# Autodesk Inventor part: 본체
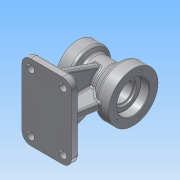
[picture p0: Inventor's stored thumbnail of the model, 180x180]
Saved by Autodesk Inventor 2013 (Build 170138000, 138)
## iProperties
Created: 2015-08
Part Number: 본체
Material: 알루미늄 6061
Document SubType Name: Modeling
Designer: ST3
Density: 2.71 g/cm^3
Mass: 1076.88 g
Surface Area: 747.39 cm^2
Volume: 397.374 cm^3
Author: ST3
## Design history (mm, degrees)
sketch "스케치1"
  geometry: L1 (0, 0)-(35.699, 0); L2 (-45, 35)-(-25, 35); L3 (-25, 35)-(-19.804, 26); L4 (-19.804, 26)-(8.315, 26); L5 (8.315, 26)-(25, 40); L6 (25, 40)-(45, 40); L7 (45, 40)-(45, 26); L8 (28, 16)-(-22, 16); L9 (-45, 20)-(-45, 35); L10 (0, 0)-(0, -43.803); L11 (-45, 20)-(-22, 20); L12 (-22, 20)-(-22, 16); L13 (45, 26)-(31, 26); L14 (31, 26)-(31, 19); L15 (31, 19)-(28, 19); L16 (28, 19)-(28, 16)
  constraints: 32 end point, 9 parallel, 4 perpendicular, 1 horizontal
  dimensions: "d4" = 20 distance of L2.start L2.end; "d5" = 20 distance of L5.end L6.end; "d7" = 40 deg angle of L4 L5; "d15" = 90 distance between parallel lines of L7 L9; "d17" = 32 diameter of L8 L1; "d18" = 80 diameter of L6 L1; "d19" = 70 diameter of L2 L1; "d23" = 52 diameter of L4 L1; "d112" = 40 diameter of L11 L1; "d113" = 52 diameter of L13 L1; "d114" = 38 diameter of L15 L1; "d115" = 3 distance of L14.end L15.end; "d116" = 60 deg angle of L4 L3
revolve "회전1" sketch "스케치1" stored, may be unused: angle "d28" = 90 deg
node "작업 평면1"
sketch "스케치2"
  geometry: L1 (-45, -35)-(-25, -35) reference; L2 (25, -40)-(45, -40) reference; L3 (-45, -90)-(-45, -78); L4 (-45, -78)-(35, -78); L5 (35, -78)-(35, -90); L6 (-45, -35)-(-45, 35) reference; L7 (-45, -90)-(35, -90); 1 further point
  constraints: 8 end point, 1 parallel, 1 perpendicular
  dimensions: "d34" = 0 distance between parallel lines of L6 L3; "d36" = 90 distance from line of point (0, 0) L7; "d37" = 80 distance of L3.end L4.end; "d38" = 12 distance of L4.end L5.end
extrude "돌출1" join sketch "스케치2" stored distance "d39" = 122; taper "d40" = 0 deg
node "작업 평면2"
sketch "스케치4"
  geometry: L1 (-45, -78)-(35, -78) reference; L2 (-45, -90)-(-45, -78) reference; L3 (-45, -78)-(35, -78) reference; L4 (35, -78)-(35, -90) reference; L5 (35, -90)-(-45, -90) reference; L6 (-45, -35)-(-25, -35) reference; L7 (-19.804, -26)-(8.315, -26) reference; L8 (25, -40)-(45, -40) reference; L9 (-25, -35)-(-19.804, -26) reference; L10 (8.315, -26)-(25, -40) reference; L11 (-35, -78)-(-35, -35); L12 (25, -78)-(31.7, -40); L13 (-35, -35)-(-35, -25.572); L14 (-35, -25.572)-(31.7, -26); L15 (31.7, -40)-(32.614, -34.816); L16 (32.614, -34.816)-(31.7, -26); 1 further point
  constraints: 12 end point, 4 point on line, 2 collinear, 1 midpoint, 1 perpendicular
  dimensions: "d42" = 10 distance between parallel lines of L11 L2; "d44" = 80 deg angle of L1 L12; "d45" = 10 distance of L1.end L12.start
extrude "돌출2" join sketch "스케치4" stored distance "d46" = 12; taper "d47" = 0 deg
sketch "스케치5"
  geometry: L1 (28.973, 0)-(0, 0) reference; 3 further points
  constraints: 3 other
extrude "돌출3" join sketch "스케치5" stored distance "d48" = 12; taper "d49" = 0 deg
sketch "스케치6"
  geometry: L1 (0, 0)-(28.973, 0) reference; 3 further points
  constraints: 3 other
extrude "돌출4" join sketch "스케치6" stored distance "d50" = 12; taper "d51" = 0 deg
node "작업 평면3"
sketch "스케치7"
  geometry: L1 (0, 12)-(122, 12) reference; L2 (10, 12)-(35.909, 83.185); L3 (112, 12)-(86.091, 83.185); A1 r 26 centre (61, 90) between (67, 64.702) and (55, 64.702) reference; 1 further point
  constraints: 4 end point, 2 point on circle, 2 point on line
  dimensions: "d52" = 10 distance of L1.start L2.start; "d53" = 70 deg angle of L1 L2; "d54" = 10 distance of L1.end L3.start; "d55" = 70 deg angle of L1 L3
extrude "돌출5" join sketch "스케치7" stored distance "d56" = 12; taper "d57" = 0 deg
fillet "모깎기1" dims "d82" = 5
sketch "스케치10"
  geometry: L1 (67, 12)-(67, 64.702) reference; L2 (112, 12)-(67, 12) reference; L3 (112, 12)-(86.091, 83.185) reference; L4 (4.674, 30)-(120.153, 30); L5 (37, 40.448)-(37, 24); L6 (85, 38.314)-(85, 25.447); L7 (0, 12)-(122, 12) reference; L8 (61, 12)-(61, 38.306); L9 (31, 30)-(31, 36); L10 (43, 30)-(43, 36); L11 (79, 30)-(79, 37.447); L12 (91, 30)-(91, 37.447); L13 (37, 42)-(44.916, 42); L14 (85, 43.447)-(79, 43.447); A1 r 26 centre (61, 90) between (67, 64.702) and (86.091, 83.185) reference; A2 r 6 centre (37, 30) between (31, 30) and (43, 30); A3 r 6 centre (85, 30) between (79, 30) and (91, 30); A4 r 6 centre (37, 36) between (31, 36) and (43, 36); A5 r 6 centre (85, 37.447) between (79, 37.447) and (79, 37.447)
  constraints: 20 end point, 12 point on circle, 11 point on line, 6 tangent, 4 centre point, 4 parallel, 4 perpendicular, 1 midpoint
  dimensions: "d83" = 18 distance between parallel lines of L2 L4; "d84" = 24 distance between parallel lines of L5 L8; "d85" = 48 distance between parallel lines of L5 L6; "d86" = 12 diameter of A2; "d87" = 12 diameter of A3; "d88" = 12 diameter of A4; "d89" = 12 diameter of A5; "d91" = 18 distance from line of L6.end L14; "d92" = 18 distance of L13.start L5.end
extrude "돌출6" cut sketch "스케치10" stored distance "d93" = 12; taper "d94" = 0 deg
node "작업 평면4"
fillet "모깎기2" dims "d95" = 3
fillet "모깎기3" dims "d96" = 3
fillet "모깎기4" dims "d97" = 14
sketch "스케치11"
  geometry: C1 r 6 at (0, 108); C2 r 6 at (52, 108); C3 r 6 at (0, 14); C4 r 6 at (52, 14); A1 r 14 centre (0, 14) between (-14, 14) and (0, 0) reference; A2 r 14 centre (52, 14) between (52, 0) and (66, 14) reference; A3 r 14 centre (52, 108) between (66, 108) and (52, 122) reference; A4 r 14 centre (0, 108) between (0, 122) and (-14, 108) reference; 1 further point
  constraints: 4 centre point, 4 coincident
  dimensions: "d100" = 12 diameter of C3; "d101" = 12 diameter of C1; "d102" = 12 diameter of C2; "d103" = 12 diameter of C4
extrude "돌출7" cut sketch "스케치11" stored distance "d104" = 12; taper "d105" = 0 deg
sketch "스케치12"
  geometry: C1 r 16 at (0, 0) reference
extrude "돌출8" cut sketch "스케치12" stored distance "d106" = 12; taper "d107" = 0 deg
sketch "스케치13"
  geometry: C1 r 20 at (0, 0) reference
extrude "돌출9" cut sketch "스케치13" stored distance "d109" = 12; taper "d110" = 0 deg
sketch "스케치14" dims "d117" = 66
  geometry: C1 r 40 at (0, 0) reference; C2 r 2.189 at (0, 33); 1 further point
  constraints: 1 centre point, 1 coincident, 1 vertical alignment, 2 other
hole "구멍3" sketch "스케치14" at (0, 33) diameter "d119" = 3.242; stored, may be unused: countersink angle "d123" = 90 deg, drill point angle "d125" = 118 deg; dims "d120" = 10, "d121" = 4, "d122" = 2, "d124" = 13
sketch "스케치15" dims "d129" = 54
  geometry: C1 r 20 at (0, 0) reference; C2 r 2.341 at (0, 27); 1 further point
  constraints: 1 centre point, 1 coincident, 1 vertical alignment, 2 other
hole "구멍4" sketch "스케치15" at (0, 27) diameter "d131" = 3.242; stored, may be unused: countersink angle "d135" = 90 deg, drill point angle "d137" = 118 deg; dims "d132" = 10, "d133" = 4, "d134" = 2, "d136" = 13
fillet "모깎기5" dims "d141" = 3
fillet "모깎기6" dims "d142" = 0.3
chamfer "모따기1" distance "d143" = 1; stored, may be unused: second distance "d144" = 2, angle "d145" = 45 deg
chamfer "모따기2" distance "d146" = 1; stored, may be unused: second distance "d147" = 2, angle "d148" = 45 deg
fillet "모깎기7" dims "d149" = 3
fillet "모깎기8" dims "d150" = 3
fillet "모깎기9" dims "d151" = 3
fillet "모깎기10" dims "d152" = 3
sketch "스케치16"
  geometry: L1 (-35, -37.881)-(-35, -75) reference; L2 (21, -78)-(-31, -78) reference; L3 (-35, -54)-(-19, -54); L4 (-19, -54)-(-19, -65.099); L5 (-22.002, -74.739)-(-22.002, -33.261); L6 (-22.002, -33.261)-(-15.998, -33.261); L7 (-15.998, -33.261)-(-15.998, -74.739); L8 (-15.998, -74.739)-(-22.002, -74.739); L9 (-22.002, -74.739)-(-15.998, -33.261); L10 (-22.002, -33.261)-(-15.998, -74.739); L11 (-19, -54)-(-31.507, -54); 1 further point
  constraints: 10 end point, 2 parallel, 1 midpoint, 1 perpendicular, 1 point on line, 2 other
  dimensions: "d153" = 24 distance between parallel lines of L2 L3; "d154" = 16 distance between parallel lines of L1 L4; "d155" = 0 distance of L3.end L11.start; "d156" = 0 distance of L3.end L11.start
extrude "돌출10" join sketch "스케치16" distance "d157" = 0.5; taper "d158" = 0 deg
node "솔리드1"
mirror "대칭1"
pattern_circular "원형 패턴3" dims angle "d127" = 360 deg
pattern_circular "원형 패턴4" dims angle "d139" = 360 deg
node "투영된 루프1"
node "투영된 루프2"
other parameters: "d29" = 0, "d41" = 0
